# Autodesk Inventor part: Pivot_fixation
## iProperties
Shininess: 20.0
Length Units: 11269
Angle Units: 11279
Time Units: 11290
Mass Units: 11283
Length Display Precision: 3
Angle Display Precision: 2
Created: 2004-05
Part Number: Pivot_fixation
Material: Par défaut
Document SubType Name: Modélisation
Designer: Danielc
Density: 0.0
Volumn: 0.0
Area: 0.0
PropertySet Name: Model Information
Control State: 0
Master: False
Checked Out: False
Author: Danielc
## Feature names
1. Révolution1 [Revolution]
2. Perçage1 [Hole]
3. Extrusion2
4. Révolution2 [Revolution]
5. Révolution3 [Revolution]
